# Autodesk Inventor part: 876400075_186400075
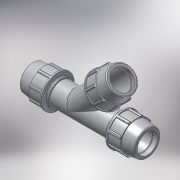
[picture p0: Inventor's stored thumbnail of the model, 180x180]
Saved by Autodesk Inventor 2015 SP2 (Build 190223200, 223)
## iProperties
Created: 2017-02
Part Number: 876400075_186400075
Material: PVC-Piping
Description: PLASSON 45° TEE 75-75-75
Document SubType Name: Modeling
Designer: KIM
Mass: 92.6774 g
Surface Area: 199.44 cm^2
Volume: 66.1981 cm^3
Density: 1.4 g/cm^3
Appearance: Smooth - White
Author: KIM
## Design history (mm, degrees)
derived "87640.ipt"
feature "Solid1::87640.ipt"
feature "Solid3::87640.ipt"
tag "TaggingFeature1"
body "Solid1"
other parameters: "d2" = 75, "d4" = 18.58333, "d5" = 44.6, "d7" = 132, "d11" = 7.43333, "d13" = 120 deg, "d14" = 97.5, "d15" = 8 deg, "d16" = 105.6, "d18" = 3.75, "d19" = 35 deg, "d20" = 17.5 deg, "d21" = 122.76, "d23" = 0, "d25" = 360 deg, "d27" = 2.64, "d33" = 1.5, "d42" = 53.52, "d43" = 3.96, "d46" = 2.25, "d68" = 6.69, "d91" = 92.4, "d93" = 137, "d95" = 67.5, "d134" = 223, "d138" = 45 deg, "d141" = 204, "d144" = 0, "d146" = 0, "d150" = 3.75, "d158" = 1.5, "d159" = 5.28, "d160" = 0, "d165" = 260.3, "d166" = 122.76, "d167" = 35 deg, "d168" = 17.5 deg, "d170" = 0, "d172" = 360 deg, "d174" = 3.96, "d177" = 2.64, "d180" = 5.28, "d181" = 0, "d_" = 75, "E_" = 132, "A_" = 204, "l_" = 137, "H_" = 446
